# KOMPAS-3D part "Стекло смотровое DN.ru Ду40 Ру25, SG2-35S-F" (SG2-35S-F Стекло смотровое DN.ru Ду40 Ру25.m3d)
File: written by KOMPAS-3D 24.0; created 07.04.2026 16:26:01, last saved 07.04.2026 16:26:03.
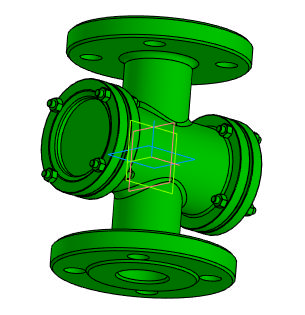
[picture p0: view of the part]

Document properties: Автор: Main; Полное имя файла: D:\DN.ru Аутсерс\Стекло смотровое DN.ru\SG2-35S-F Стекло смотровое DN.ru Ду40 Ру25\SG2-35S-F Стекло смотровое DN.ru Ду40 Ру25.m3d

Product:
- Body: Тело 1  | qty 1
    Масса: 7.458074
- Part/product: Стекло смотровое DN.ru Ду40 Ру25  | designation SG2-35S-F
    Масса: 9
    Раздел спецификации: Прочие изделия
    Примечание: D500-00095

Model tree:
1. Операция без истории:1

Expressions: SG2-35S-F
